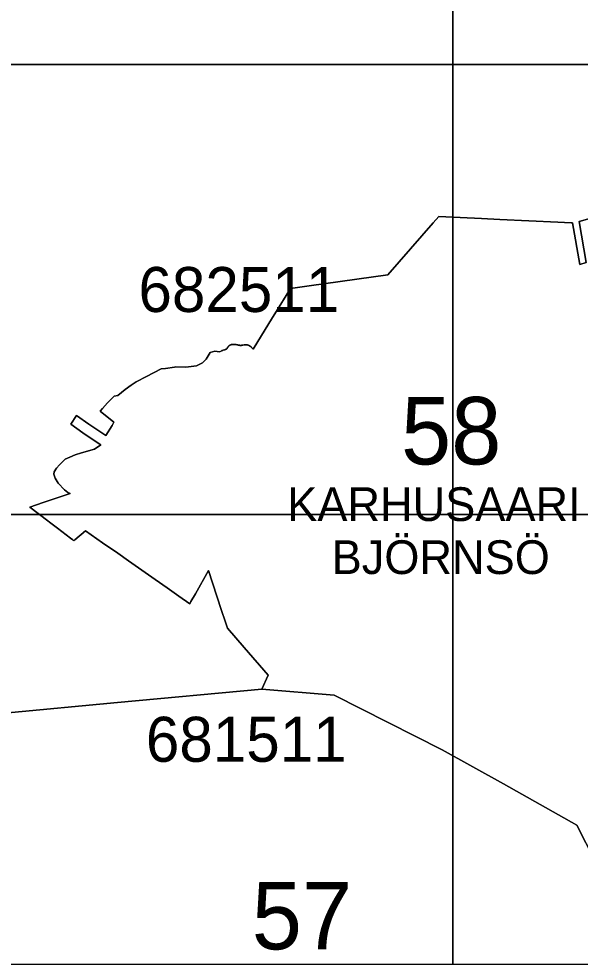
# Model space of a CAD drawing. Extents: x 25485000 to 25520000, y 6656775 to 6690000.
# Drawn here: x 25511036 to 25512283, y 6681015 to 6683102 of the extents above; entities that cross this region are included whole.
import ezdxf

# ---------------------------------------------------------------- set-up
doc = ezdxf.new("R2010")
doc.units = 0
doc.layers.add('Level 63', color=7, linetype='Continuous')

msp = doc.modelspace()

# ---------------------------------------------------------------- linework, layer by layer
at = {"layer": 'Level 63'}
for points in [[(25511000, 6683000), (25512000, 6683000), (25512000, 6684000), (25511000, 6684000)], [(25512000, 6683000), (25513000, 6683000), (25513000, 6684000), (25512000, 6684000)], [(25511000, 6682000), (25512000, 6682000), (25512000, 6683000), (25511000, 6683000)], [(25512000, 6682000), (25513000, 6682000), (25513000, 6683000), (25512000, 6683000)], [(25511000, 6681000), (25512000, 6681000), (25512000, 6682000), (25511000, 6682000)], [(25512000, 6681000), (25513000, 6681000), (25513000, 6682000), (25512000, 6682000)]]:
    msp.add_lwpolyline(points, close=True, dxfattribs=at)
for points in [[(25511003.9, 6681558.2), (25511254.8, 6681581.6), (25511576, 6681611.5), (25511589.6, 6681642.6), (25511536.9, 6681703.8), (25511499.2, 6681746.7), (25511494.8, 6681760.2), (25511485.7, 6681788.2), (25511457.3, 6681875.5), (25511428.1, 6681823.6), (25511418.2, 6681806), (25511415.7, 6681801.4), (25511391.6, 6681818.2), (25511365.1, 6681836.8), (25511338.4, 6681855.5), (25511279.6, 6681896.7), (25511255.5, 6681913.6), (25511221.9, 6681937.1), (25511183.9, 6681963.8), (25511160.2, 6681943.5), (25511158.1, 6681941.6), (25511155.5, 6681943.6), (25511150.6, 6681947.3), (25511121.3, 6681969.6), (25511103.9, 6681982.8), (25511103.9, 6681982.8), (25511100.5, 6681985.4), (25511060.1, 6682016.1), (25511089.5, 6682026.1), (25511102.8, 6682030.6), (25511150.1, 6682046.6), (25511144.6, 6682048.9), (25511137.5, 6682054.6), (25511123.2, 6682069.6), (25511116.8, 6682080.4), (25511113.8, 6682089.4), (25511114.4, 6682094.6), (25511119.2, 6682102.6), (25511126.3, 6682110), (25511138.7, 6682122.8), (25511148.8, 6682127.6), (25511160.6, 6682132.4), (25511174.9, 6682137), (25511204.2, 6682145.3), (25511217.7, 6682154.8), (25511214.3, 6682157.1), (25511177.7, 6682181.4), (25511151.4, 6682200.4), (25511163.9, 6682220.1), (25511191.4, 6682200.7), (25511229.2, 6682175.6), (25511243.3, 6682197.7), (25511247.1, 6682205), (25511216.2, 6682229.5), (25511221.4, 6682235.5), (25511232.6, 6682248.3), (25511247.9, 6682263.1), (25511255.9, 6682264), (25511264, 6682270.9), (25511272.1, 6682277.8), (25511285.2, 6682287.6), (25511296.3, 6682294.4), (25511319.1, 6682306.3), (25511351.8, 6682323.5), (25511361.8, 6682324.4), (25511381.4, 6682327.5), (25511384.8, 6682328), (25511406.8, 6682327.7), (25511418.9, 6682328.5), (25511424.9, 6682329.4), (25511430.9, 6682330.3), (25511444, 6682337.1), (25511452.1, 6682345), (25511461.3, 6682359.9), (25511471.4, 6682362.7), (25511481.4, 6682361.6), (25511485.3, 6682363.1), (25511486.2, 6682363.6), (25511487.1, 6682364.1), (25511487.2, 6682364.2), (25511487.4, 6682364.2), (25511487.6, 6682364.3), (25511487.8, 6682364.4), (25511488, 6682364.5), (25511488.4, 6682364.6), (25511488.8, 6682364.7), (25511490.2, 6682365.2), (25511491.7, 6682365.6), (25511492.6, 6682365.9), (25511493.3, 6682366.1), (25511494, 6682366.3), (25511494.5, 6682366.5), (25511494.8, 6682366.6), (25511495.1, 6682366.7), (25511495.3, 6682366.8), (25511495.5, 6682366.9), (25511495.9, 6682367.1), (25511496.3, 6682367.3), (25511496.6, 6682367.5), (25511496.9, 6682367.7), (25511497.1, 6682367.8), (25511497.3, 6682368), (25511497.4, 6682368.1), (25511497.6, 6682368.2), (25511497.8, 6682368.3), (25511497.9, 6682368.5), (25511498.2, 6682368.8), (25511498.5, 6682369.1), (25511498.6, 6682369.3), (25511498.9, 6682369.6), (25511499.1, 6682370), (25511499.3, 6682370.2), (25511499.7, 6682370.9), (25511500.1, 6682371.5), (25511500.4, 6682371.9), (25511500.7, 6682372.4), (25511501, 6682372.9), (25511501.2, 6682373.2), (25511501.5, 6682373.6), (25511501.7, 6682373.8), (25511501.9, 6682374), (25511502, 6682374.1), (25511502.2, 6682374.3), (25511502.5, 6682374.6), (25511502.8, 6682374.9), (25511503, 6682375), (25511503.3, 6682375.3), (25511503.5, 6682375.4), (25511503.7, 6682375.6), (25511503.9, 6682375.7), (25511504.3, 6682375.9), (25511504.5, 6682376), (25511504.7, 6682376.2), (25511505.1, 6682376.4), (25511505.4, 6682376.6), (25511505.7, 6682376.7), (25511506, 6682376.8), (25511506.3, 6682376.9), (25511506.5, 6682377), (25511507, 6682377.2), (25511507.4, 6682377.3), (25511507.7, 6682377.4), (25511508.2, 6682377.5), (25511508.4, 6682377.6), (25511509, 6682377.7), (25511509.5, 6682377.8), (25511509.9, 6682377.9), (25511510.4, 6682377.9), (25511510.9, 6682378), (25511511.5, 6682378.1), (25511511.9, 6682378.1), (25511512.4, 6682378.1), (25511512.9, 6682378.1), (25511513.5, 6682378.2), (25511513.9, 6682378.1), (25511514.4, 6682378.1), (25511514.9, 6682378.1), (25511515.5, 6682378.1), (25511515.9, 6682378), (25511516.3, 6682378), (25511516.6, 6682377.9), (25511516.8, 6682377.9), (25511516.9, 6682377.9), (25511517.6, 6682377.8), (25511518.4, 6682377.6), (25511518.9, 6682377.5), (25511520, 6682377.3), (25511521.1, 6682377), (25511523.3, 6682376.5), (25511524.7, 6682376.2), (25511525.3, 6682376.1), (25511525.8, 6682376), (25511526.2, 6682376), (25511526.7, 6682375.9), (25511527.1, 6682375.8), (25511527.5, 6682375.8), (25511527.8, 6682375.8), (25511528.2, 6682375.8), (25511528.7, 6682375.7), (25511528.9, 6682375.7), (25511529.2, 6682375.7), (25511529.4, 6682375.8), (25511529.6, 6682375.8), (25511530.3, 6682375.8), (25511531.1, 6682375.9), (25511531.6, 6682376), (25511532.7, 6682376.1), (25511533.8, 6682376.3), (25511536, 6682376.7), (25511537.5, 6682376.9), (25511538.1, 6682377), (25511538.6, 6682377), (25511539, 6682377.1), (25511539.5, 6682377.1), (25511539.9, 6682377.1), (25511540.3, 6682377.1), (25511540.6, 6682377.1), (25511541, 6682377.1), (25511541.5, 6682377.1), (25511541.9, 6682377.1), (25511542.2, 6682377), (25511542.5, 6682377), (25511542.8, 6682377), (25511543.2, 6682376.9), (25511543.4, 6682376.8), (25511543.9, 6682376.7), (25511544.4, 6682376.6), (25511544.7, 6682376.5), (25511545.1, 6682376.3), (25511545.4, 6682376.3), (25511545.8, 6682376.1), (25511546.2, 6682376), (25511546.4, 6682375.9), (25511546.8, 6682375.7), (25511547.2, 6682375.5), (25511547.6, 6682375.3), (25511548, 6682375.1), (25511548.2, 6682375), (25511548.5, 6682374.8), (25511549, 6682374.5), (25511549.3, 6682374.3), (25511549.7, 6682374), (25511549.9, 6682373.9), (25511550.2, 6682373.7), (25511550.6, 6682373.3), (25511551, 6682373), (25511551.4, 6682372.7), (25511551.7, 6682372.4), (25511552, 6682372.1), (25511552.2, 6682371.9), (25511552.6, 6682371.6), (25511552.9, 6682371.2), (25511553.1, 6682371), (25511553.4, 6682370.6), (25511553.6, 6682370.4), (25511554.9, 6682368.9), (25511556.2, 6682367.4), (25511599.4, 6682437.6), (25511604.6, 6682445.9), (25511639.2, 6682502.1), (25511680.7, 6682507.9), (25511855.8, 6682532.3), (25511956.7, 6682648.3), (25511969.3, 6682662.7), (25512063.9, 6682658), (25512104.7, 6682656), (25512234, 6682649.5), (25512263.1, 6682648.1), (25512266, 6682647.9), (25512282.5, 6682555.4), (25512296.9, 6682559.7), (25512281, 6682651), (25512331.5, 6682665.4)], [(25512331.5, 6682665.4), (25512281, 6682651), (25512296.9, 6682559.7), (25512282.5, 6682555.4), (25512266, 6682647.9), (25512263.1, 6682648.1), (25512234, 6682649.5), (25512104.7, 6682656), (25512063.9, 6682658), (25511969.3, 6682662.7), (25511956.7, 6682648.3), (25511855.8, 6682532.3), (25511680.7, 6682507.9), (25511639.2, 6682502.1), (25511604.6, 6682445.9), (25511599.4, 6682437.6), (25511556.2, 6682367.4), (25511554.9, 6682368.9), (25511553.6, 6682370.4), (25511553.3, 6682370.8), (25511553, 6682371.1), (25511552.8, 6682371.3), (25511552.6, 6682371.5), (25511552.2, 6682371.9), (25511551.9, 6682372.2), (25511551.6, 6682372.5), (25511551.3, 6682372.7), (25511551, 6682373), (25511550.6, 6682373.3), (25511550.2, 6682373.6), (25511549.9, 6682373.9), (25511549.7, 6682374), (25511549.4, 6682374.2), (25511549, 6682374.5), (25511548.6, 6682374.7), (25511548.2, 6682374.9), (25511548, 6682375.1), (25511547.7, 6682375.3), (25511547.2, 6682375.5), (25511546.8, 6682375.7), (25511546.4, 6682375.8), (25511546.2, 6682375.9), (25511545.8, 6682376.1), (25511545.4, 6682376.3), (25511545, 6682376.4), (25511544.6, 6682376.5), (25511544.3, 6682376.6), (25511543.9, 6682376.7), (25511543.4, 6682376.8), (25511543, 6682376.9), (25511542.6, 6682377), (25511542.3, 6682377), (25511542, 6682377.1), (25511541.7, 6682377.1), (25511541.5, 6682377.1), (25511541, 6682377.1), (25511540.5, 6682377.1), (25511540.2, 6682377.1), (25511539.8, 6682377.1), (25511539.5, 6682377.1), (25511538.9, 6682377.1), (25511538.4, 6682377), (25511538, 6682377), (25511537.5, 6682376.9), (25511536.4, 6682376.8), (25511535.3, 6682376.6), (25511533.1, 6682376.2), (25511531.6, 6682376), (25511531.2, 6682375.9), (25511530.8, 6682375.9), (25511530.1, 6682375.8), (25511529.6, 6682375.8), (25511529.3, 6682375.8), (25511529.1, 6682375.7), (25511528.9, 6682375.7), (25511528.7, 6682375.7), (25511528.3, 6682375.7), (25511527.8, 6682375.8), (25511527.6, 6682375.8), (25511527.2, 6682375.8), (25511526.7, 6682375.9), (25511526.1, 6682376), (25511525.6, 6682376), (25511525.2, 6682376.1), (25511524.7, 6682376.2), (25511523.6, 6682376.4), (25511522.5, 6682376.7), (25511520.3, 6682377.2), (25511518.9, 6682377.5), (25511518.1, 6682377.7), (25511517.4, 6682377.8), (25511516.9, 6682377.9), (25511516.8, 6682377.9), (25511516.7, 6682377.9), (25511516.5, 6682378), (25511516.3, 6682378), (25511515.8, 6682378), (25511515.2, 6682378.1), (25511514.9, 6682378.1), (25511514.4, 6682378.1), (25511514.1, 6682378.1), (25511513.8, 6682378.1), (25511513.2, 6682378.1), (25511512.9, 6682378.1), (25511512.4, 6682378.1), (25511511.8, 6682378.1), (25511511.2, 6682378), (25511510.9, 6682378), (25511510.4, 6682377.9), (25511510.1, 6682377.9), (25511509.8, 6682377.9), (25511509.3, 6682377.8), (25511508.9, 6682377.7), (25511508.4, 6682377.6), (25511508, 6682377.5), (25511507.6, 6682377.4), (25511507.3, 6682377.3), (25511507, 6682377.2), (25511506.5, 6682377), (25511506.1, 6682376.9), (25511505.8, 6682376.7), (25511505.6, 6682376.6), (25511505.3, 6682376.5), (25511504.9, 6682376.3), (25511504.7, 6682376.2), (25511504.4, 6682376), (25511504.1, 6682375.8), (25511503.9, 6682375.7), (25511503.7, 6682375.6), (25511503.4, 6682375.3), (25511503.2, 6682375.2), (25511503, 6682375), (25511502.7, 6682374.8), (25511502.4, 6682374.5), (25511502.2, 6682374.3), (25511502, 6682374.1), (25511501.8, 6682373.9), (25511501.7, 6682373.8), (25511501.5, 6682373.6), (25511501.2, 6682373.1), (25511500.9, 6682372.6), (25511500.6, 6682372.3), (25511500.4, 6682371.9), (25511500.2, 6682371.6), (25511500, 6682371.3), (25511499.6, 6682370.7), (25511499.3, 6682370.2), (25511499, 6682369.9), (25511498.7, 6682369.5), (25511498.5, 6682369.2), (25511498.3, 6682368.9), (25511498.1, 6682368.7), (25511497.9, 6682368.5), (25511497.8, 6682368.3), (25511497.6, 6682368.2), (25511497.4, 6682368.1), (25511497.3, 6682367.9), (25511497, 6682367.8), (25511496.9, 6682367.7), (25511496.7, 6682367.6), (25511496.5, 6682367.5), (25511496.3, 6682367.3), (25511495.9, 6682367.1), (25511495.6, 6682366.9), (25511495.3, 6682366.8), (25511495, 6682366.7), (25511494.8, 6682366.6), (25511494.5, 6682366.5), (25511493.8, 6682366.2), (25511493.1, 6682366), (25511492.6, 6682365.9), (25511491.2, 6682365.4), (25511489.7, 6682365), (25511488.8, 6682364.7), (25511488.1, 6682364.5), (25511487.9, 6682364.4), (25511487.6, 6682364.3), (25511487.5, 6682364.3), (25511487.3, 6682364.2), (25511487.1, 6682364.1), (25511486.2, 6682363.6), (25511485.3, 6682363.1), (25511481.4, 6682361.6), (25511471.4, 6682362.7), (25511461.3, 6682359.9), (25511452.1, 6682345), (25511444, 6682337.1), (25511430.9, 6682330.3), (25511424.9, 6682329.4), (25511418.9, 6682328.5), (25511406.8, 6682327.7), (25511384.8, 6682328), (25511381.4, 6682327.5), (25511361.8, 6682324.4), (25511351.8, 6682323.5), (25511319.1, 6682306.3), (25511296.3, 6682294.4), (25511285.2, 6682287.6), (25511272.1, 6682277.8), (25511264, 6682270.9), (25511255.9, 6682264), (25511247.9, 6682263.1), (25511232.6, 6682248.3), (25511221.4, 6682235.5), (25511216.2, 6682229.5), (25511247.1, 6682205), (25511243.3, 6682197.7), (25511229.2, 6682175.6), (25511191.4, 6682200.7), (25511163.9, 6682220.1), (25511151.4, 6682200.4), (25511177.7, 6682181.4), (25511214.3, 6682157.1), (25511217.7, 6682154.8), (25511204.2, 6682145.3), (25511174.9, 6682137), (25511160.6, 6682132.4), (25511148.8, 6682127.6), (25511138.7, 6682122.8), (25511126.3, 6682110), (25511119.2, 6682102.6), (25511114.4, 6682094.6), (25511113.8, 6682089.4), (25511116.8, 6682080.4), (25511123.2, 6682069.6), (25511137.5, 6682054.6), (25511144.6, 6682048.9), (25511150.1, 6682046.6), (25511102.8, 6682030.6), (25511089.5, 6682026.1), (25511060.1, 6682016.1), (25511100.5, 6681985.4), (25511103.9, 6681982.8), (25511103.9, 6681982.8), (25511121.3, 6681969.6), (25511150.6, 6681947.3), (25511155.5, 6681943.6), (25511158.1, 6681941.6), (25511160.2, 6681943.5), (25511183.9, 6681963.8), (25511221.9, 6681937.1), (25511255.5, 6681913.6), (25511279.6, 6681896.7), (25511338.4, 6681855.5), (25511365.1, 6681836.8), (25511391.6, 6681818.2), (25511415.7, 6681801.4), (25511418.2, 6681806), (25511428.1, 6681823.6), (25511457.3, 6681875.5), (25511485.7, 6681788.2), (25511494.8, 6681760.2), (25511499.2, 6681746.7), (25511536.9, 6681703.8), (25511589.6, 6681642.6), (25511576, 6681611.5), (25511736.3, 6681597.8), (25511976.6, 6681476.5), (25512113.2, 6681400.7), (25512276.1, 6681309.3), (25512357.7, 6681149.2)], [(25512357.7, 6681149.2), (25512276.1, 6681309.3), (25512113.2, 6681400.7), (25511976.6, 6681476.5), (25511736.3, 6681597.8), (25511576, 6681611.5), (25511254.8, 6681581.6), (25511003.9, 6681558.2)]]:
    msp.add_lwpolyline(points, dxfattribs=at)

# ---------------------------------------------------------------- texts
for s, height, p in [('682511', 100, (25511301.6, 6682450)), ('58', 150, (25511885.1, 6682111.1)), ('KARHUSAARI', 75, (25511632.3, 6681985.3)), ('BJÖRNSÖ', 75, (25511731, 6681867.4)), ('681511', 100, (25511318.1, 6681450)), ('57', 150, (25511553.4, 6681033))]:
    msp.add_text(s, height=height, dxfattribs=at).set_placement(p)

doc.saveas('drawing.dxf')
